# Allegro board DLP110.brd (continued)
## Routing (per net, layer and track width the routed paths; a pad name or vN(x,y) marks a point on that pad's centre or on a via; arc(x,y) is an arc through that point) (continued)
P1_A2: length 49.8
  TOP w0.267: v1(25.15,9.14) 25.41,9.41 27.48,9.41 27.75,9.67 J9.63 ; RN1.8 13.88,44.41 v1(14.1,44.18)
  05_SIG2 w0.102: v1(14.1,44.18) 14.82,43.46 16.75,43.46 19.18,41.03 19.18,36.45 22.99,32.64 22.99,25.78 24.13,24.64 24.13,19.65 24.64,19.15 24.64,9.65 v1(25.15,9.14)
  BOTTOM w0.267: v1(25.15,9.14) 25.4,9.4 27.48,9.4 27.75,9.66 J500.63
P1_A3: length 52.5
  TOP w0.267: J9.62 27.25,6.03 27.15,6.12 25.88,6.12 v1(25.07,6.93) ; v1(12.89,43.94) 12.89,44.95 13.38,45.44 RN1.7
  05_SIG2 w0.102: v1(25.07,6.93) 25.07,8.41 24.27,9.21 24.27,18.97 23.72,19.52 23.72,24.48 22.58,25.61 22.58,32.28 18.67,36.19 18.67,40.22 16.76,42.13 14.7,42.13 v1(12.89,43.94)
  BOTTOM w0.267: J500.62 27.25,5.97 27.08,6.13 25.87,6.13 v1(25.07,6.93)
P1_A4: length 51.2
  TOP w0.267: J9.61 24.93,11.09 v1(23.5,9.65) ; RN1.6 13.3,45.94 v1(11.85,44.49)
  05_SIG2 w0.102: v1(11.85,44.49) 11.85,43.61 18.22,37.24 18.22,35.89 22.05,32.05 22.05,25.44 23.15,24.34 23.15,19.51 23.8,18.85 23.8,9.96 v1(23.5,9.65)
  BOTTOM w0.267: v1(23.5,9.65) 24.71,10.87 J500.61
P1_A5: length 51.3
  TOP w0.267: v1(22.35,6.86) 21.75,6.25 J9.60 ; v1(11.54,45.82) 12.55,45.82 13.17,46.44 RN1.5
  05_SIG2 w0.102: v1(11.54,45.82) 11.2,45.47 11.2,43.64 17.65,37.19 17.65,35.69 21.55,31.79 21.55,25.2 22.78,23.98 22.78,19.27 23.38,18.67 23.38,11.57 22.35,10.54 v1(22.35,6.86)
  BOTTOM w0.267: v1(22.35,6.86) 21.75,6.25 J500.60
P1_A6: length 45.3
  TOP w0.267: v1(12.45,46.74) 12.65,46.94 RN1.4 ; v1(22.48,12.32) 21.75,11.59 J9.59
  05_SIG2 w0.102: v1(12.45,46.74) 11.56,46.74 10.72,45.89 10.72,43.56 17.01,37.27 17.01,35.57 21.04,31.54 21.04,15.78 22.48,14.34 v1(22.48,12.32)
  BOTTOM w0.267: J500.59 21.75,11.59 v1(22.48,12.32)
P1_A7: length 52.7
  TOP w0.267: v1(10.37,46.93) 11.72,46.93 12.23,47.44 RN1.3 ; J9.58 v1(21.25,6.97)
  05_SIG2 w0.102: v1(21.25,6.97) 21.25,12.71 20.41,13.55 20.41,13.92 20.02,14.31 20.02,31.03 13.99,37.06 13.99,38.94 9.66,43.27 9.66,46.3 10.29,46.93 v1(10.37,46.93)
  BOTTOM w0.267: J500.58 v1(21.25,6.97)
P1_A8: length 47.5
  TOP w0.267: v1(11.44,47.65) 11.88,48.09 13.12,48.09 13.27,47.94 RN1.2 ; v1(21.84,13.21) 21.25,12.61 J9.57
  05_SIG2 w0.102: v1(21.84,13.21) 21.84,14 20.53,15.31 20.53,31.29 14.41,37.4 14.41,39.13 10.15,43.39 10.15,45.83 11.24,46.92 11.24,47.45 v1(11.44,47.65)
  BOTTOM w0.267: J500.57 21.25,12.61 v1(21.84,13.21)
P1_A9: length 55.4
  TOP w0.267: J9.56 20.75,6.36 v1(20.08,7.04) ; RN1.1 13.63,48.44 13.37,48.69 10.89,48.69 v1(10.28,48.09)
  05_SIG2 w0.102: v1(20.08,7.04) 19.19,7.92 19.19,13.61 19.6,14.03 19.6,30.69 15.97,34.32 15.09,34.32 9.25,40.16 9.25,46.74 10.28,47.78 v1(10.28,48.09)
  BOTTOM w0.267: J500.56 20.75,6.36 v1(20.08,7.04)
P1_ACTDATA: length 51.7
  TOP w0.267: v1(34.42,8.99) 34.34,8.99 33.75,9.58 J9.87 ; v1(46.02,49.1) 44.83,49.1 R570.2
  05_SIG2 w0.102: v1(46.02,49.1) 42.77,45.84 42.77,42.09 39.98,39.29 39.98,29.52 36.98,26.53 36.98,17.59 33.18,13.79 33.18,10.23 v1(34.42,8.99)
  BOTTOM w0.267: v1(34.42,8.99) 33.75,9.66 J500.87
P1_B0: length 31.5
  TOP w0.267: v1(31.42,34.38) 31.42,35.78 31.11,36.09 R19.2 ; v1(30.61,12.7) 30.75,12.56 J9.75
  05_SIG2 w0.102: v1(30.61,12.7) 30.61,13.96 35.26,18.61 35.26,30.19 31.42,34.03 v1(31.42,34.38)
  BOTTOM w0.267: J500.75 30.75,12.43 v1(30.61,12.7)
P1_B1: length 38.3
  TOP w0.267: R18.2 29.72,36.27 v1(30.58,35.4) ; J9.74 30.25,6.64 v1(30.79,7.18)
  05_SIG2 w0.102: v1(30.79,7.18) 30.04,7.94 30.04,10.09 29.74,10.39 29.74,13.36 30.07,13.69 30.07,14.01 30.6,14.53 30.6,15.63 31.78,16.81 31.78,19.99 33.64,21.86 33.64,31.08 30.58,34.14 v1(30.58,35.4)
  BOTTOM w0.267: v1(30.79,7.18) 30.25,6.64 J500.74
P1_B2: length 34.2
  TOP w0.267: v1(29.97,14.78) 30.12,14.63 30.12,13.29 29.93,13.1 29.93,12.52 30.25,12.2 J9.73 ; v1(29.89,33.54) 29.69,33.74 29.69,35.38 28.29,36.78 RN2.8
  05_SIG2 w0.102: v1(29.97,14.78) 30.01,14.82 30.01,15.88 31.18,17.06 31.18,20.06 32.99,21.87 32.99,31.22 30.67,33.54 v1(29.89,33.54)
  BOTTOM w0.267: J500.73 30.25,12.2 29.95,12.5 29.95,13.2 30.12,13.42 30.12,14.63 v1(29.97,14.78)
P1_B3: length 44.2
  TOP w0.267: RN2.7 27.79,36.49 28.84,35.44 28.84,33.13 v1(30,31.97) ; v1(28.47,2.59) 29.75,3.86 J9.72
  03_SIG1 w0.147: v1(28.47,2.59) 26.92,4.14 26.92,7.66 27.44,8.18 27.44,9.17 26.69,9.92 26.69,12.78 27.28,13.37 27.28,16.63 30.23,19.58 30.23,31.74 v1(30,31.97)
  BOTTOM w0.267: J500.72 29.75,3.86 v1(28.47,2.59)
P1_B4: length 34.2
  TOP w0.267: RN2.6 27.29,36.02 v1(27.69,35.63) ; v1(29.41,13.97) 29.41,12.43 29.75,12.1 J9.71
  05_SIG2 w0.102: v1(29.41,13.97) 29.28,14.1 29.28,16.1 30.61,17.43 30.61,20.01 32.43,21.83 32.43,31.02 30.59,32.86 29.61,32.86 29.24,33.23 29.24,35.23 28.84,35.63 v1(27.69,35.63)
  BOTTOM w0.267: J500.71 29.75,12.1 29.41,12.43 v1(29.41,13.97)
P1_B5: length 36.8
  TOP w0.267: RN2.5 26.83,37.16 26.83,35.27 v1(27.66,34.45) ; J9.70 29.25,6.52 v1(29.67,6.93)
  05_SIG2 w0.102: v1(29.67,6.93) 29.67,9.65 29.17,10.15 29.17,12.98 28.67,13.48 28.67,16.4 30.1,17.83 30.1,30.43 28.88,31.65 28.88,33.23 v1(27.66,34.45)
  BOTTOM w0.267: J500.70 29.25,6.52 v1(29.67,6.93)
P1_B6: length 34.2
  TOP w0.267: v1(28.96,9.18) 29.25,9.47 J9.69 ; RN2.4 26.29,34.73 v1(27.81,33.21)
  05_SIG2 w0.102: v1(28.96,9.18) 28.65,9.49 28.65,12.84 28.23,13.27 28.23,16.89 29.71,18.37 29.71,30.29 28.47,31.53 28.47,32.56 v1(27.81,33.21)
  BOTTOM w0.267: v1(28.96,9.18) 29.25,9.47 J500.69
P1_B7: length 37.5
  TOP w0.267: RN2.3 25.79,35.69 25.69,35.59 25.69,34.45 v1(25.45,34.21) ; J9.68 v1(28.75,7.15)
  05_SIG2 w0.102: v1(25.45,34.21) 25.45,33.84 27.6,31.69 27.6,30.43 28.62,29.41 28.62,28.66 27.77,27.82 27.77,26.58 26.83,25.64 26.83,20.59 27.1,20.32 27.1,13.84 28.19,12.75 28.19,9.02 28.98,8.23 28.98,7.37 v1(28.75,7.15)
  BOTTOM w0.267: J500.68 v1(28.75,7.15)
P1_B8: length 31.9
  TOP w0.267: v1(27.53,12.57) 27.56,12.55 28.32,12.55 28.75,12.12 J9.67 ; RN2.2 25.29,35.97 24.94,35.62 v1(24.94,35.2)
  05_SIG2 w0.102: v1(27.53,12.57) 26.67,13.43 26.67,19.7 26.32,20.05 26.32,25.76 27.24,26.68 27.24,31.49 24.78,33.96 24.78,35.03 v1(24.94,35.2)
  BOTTOM w0.267: v1(27.53,12.57) 28.38,12.57 28.75,12.21 J500.67
P1_B9: length 37.3
  TOP w0.267: v1(27.64,7.21) 28.25,6.6 J9.66 ; RN2.1 24.79,36.41 v1(24.6,36.21)
  05_SIG2 w0.102: v1(24.6,36.21) 24.26,35.87 24.26,33.89 26.84,31.31 26.84,26.88 25.88,25.93 25.88,19.97 26.16,19.7 26.16,12.82 27.64,11.34 v1(27.64,7.21)
  BOTTOM w0.267: J500.66 28.25,6.6 v1(27.64,7.21)
P1_C0: length 49.7
  TOP w0.267: R31.2 v1(46.14,47.55) ; J9.85 33.25,9.17 v1(33.45,8.97)
  03_SIG1 w0.147: v1(46.14,47.55) 45.53,47.55 42.94,44.95 42.94,41.26 40.85,39.18 40.85,29.91 39.45,28.51 39.45,17.19 37.25,14.99 37.25,13.04 33.45,9.25 v1(33.45,8.97)
  BOTTOM w0.267: v1(33.45,8.97) 33.25,9.17 J500.85
P1_C1: length 52.2
  TOP w0.267: J9.84 32.75,3.77 v1(33.43,3.09) ; R30.2 v1(44.81,45.17)
  03_SIG1 w0.147: v1(44.81,45.17) 43.84,44.21 43.84,40.88 41.35,38.39 41.35,29.74 40.12,28.51 40.12,16.94 37.71,14.53 37.71,8.27 36.56,7.12 36.56,6.21 v1(33.43,3.09)
  BOTTOM w0.267: J500.84 32.75,3.77 v1(33.43,3.09)
P1_C2: length 35.9
  TOP w0.267: v1(39.32,31.55) 39.32,35.25 37.31,37.26 RN4.8 ; J9.83 32.75,9.38 v1(32.49,9.12)
  03_SIG1 w0.147: v1(39.32,31.55) 38.49,30.72 38.49,16.96 36.8,15.27 36.8,13.43 v1(32.49,9.12)
  BOTTOM w0.267: v1(32.49,9.12) 32.75,9.38 J500.83
P1_C3: length 42.2
  TOP w0.267: v1(32.38,2.98) 32.25,3.12 J9.82 ; v1(38.32,32.23) 38.32,35.33 36.81,36.84 RN4.7
  03_SIG1 w0.147: v1(32.38,2.98) 32.28,3.09 32.28,7.87 31.88,8.27 31.88,10.78 33.31,12.22 33.31,13.4 37.44,17.53 37.44,31.34 v1(38.32,32.23)
  BOTTOM w0.267: J500.82 32.25,3.12 v1(32.38,2.98)
P1_C4: length 32.4
  TOP w0.267: RN4.6 36.31,36.38 37.08,35.6 v1(37.08,34.37) ; J9.81 32.25,12.12 32.34,12.21 32.34,13.12 v1(31.75,13.72)
  03_SIG1 w0.147: v1(37.08,34.37) 36.92,34.37 36.18,33.63 36.18,18.15 v1(31.75,13.72)
  BOTTOM w0.267: v1(31.75,13.72) 32.35,13.11 32.35,12.22 32.25,12.12 J500.81
P1_C5: length 44
  TOP w0.267: v1(31.77,2.13) 31.75,2.15 J9.80 ; RN4.5 35.81,35.9 36.32,35.39 36.32,33.59 v1(36.82,33.09)
  03_SIG1 w0.147: v1(31.77,2.13) 31.57,2.33 31.57,5.64 31.78,5.85 31.78,7.77 31.53,8.01 31.53,11.34 32.71,12.51 32.71,13.76 36.82,17.87 v1(36.82,33.09)
  BOTTOM w0.267: v1(31.77,2.13) 31.75,2.15 J500.80
P1_C6: length 30.3
  TOP w0.267: J9.79 31.75,12.57 v1(31.75,12.57) ; v1(35.31,33.63) RN4.4
  03_SIG1 w0.147: v1(31.75,12.57) 31.05,13.28 31.05,14.02 35.55,18.52 35.55,33.38 v1(35.31,33.63)
  BOTTOM w0.267: v1(31.75,12.57) 31.75,12.57 J500.79
P1_C7: length 43.9
  TOP w0.267: v1(30.88,2.53) 31.25,2.9 J9.78 ; RN4.3 34.81,36.08 34.29,35.56 v1(34.29,34.09)
  03_SIG1 w0.147: v1(34.29,34.09) 34.5,33.87 34.5,33.24 35,32.74 35,18.78 30.2,13.98 30.2,13.37 29.92,13.1 29.92,12.48 30.47,11.94 30.94,11.94 31.19,11.69 31.19,7.7 31.39,7.51 31.39,6.35 30.88,5.84 v1(30.88,2.53)
  BOTTOM w0.267: v1(30.88,2.53) 31.25,2.9 J500.78
P1_C8: length 36
  TOP w0.267: v1(33.45,33.4) 33.45,35.55 34.31,36.41 RN4.2 ; v1(30.61,9.14) 31.25,9.79 J9.77
  03_SIG1 w0.147: v1(30.61,9.14) 30.61,10.88 29.4,12.08 29.4,12.85 28.65,13.6 28.65,14.7 32.34,18.39 32.34,21.42 33.45,22.53 v1(33.45,33.4)
  BOTTOM w0.267: J500.77 31.25,9.28 31.11,9.14 v1(30.61,9.14)
P1_C9: length 42.6
  TOP w0.267: v1(32.53,34.45) 32.53,35.4 33.81,36.68 RN4.1 ; v1(29.95,2.95) 30.75,3.75 J9.76
  03_SIG1 w0.147: v1(29.95,2.95) 30.25,3.25 30.25,8.11 29.9,8.46 29.9,10.82 28.83,11.88 28.83,12.71 28.18,13.36 28.18,16.02 30.74,18.59 30.74,22.13 32.53,23.92 v1(32.53,34.45)
  BOTTOM w0.267: v1(29.95,2.95) 30.75,3.75 J500.76
P1_FIELD: length 83.8
  TOP w0.267: v1(10.65,52.46) 11.29,53.09 11.29,54.07 11.79,54.57 R571.2 13.11,56.03 R39.1 ; J9.88 33.75,6.91 v1(33.96,7.12)
  05_SIG2 w0.102: v1(33.96,7.12) 32.8,5.97 18.46,5.97 17.64,6.79 17.64,13.36 19.22,14.94 19.22,30.31 15.82,33.71 14.85,33.71 11.41,37.15 10.11,37.15 8.72,38.54 8.72,47.41 10.27,48.96 12.27,48.96 13.1,49.79 13.1,51.48 12.48,52.11 11.01,52.11 v1(10.65,52.46)
  BOTTOM w0.267: J500.88 33.75,6.91 v1(33.96,7.12)
P1_HSYNC: length 59
  TOP w0.267: v1(47.26,48.66) 47.26,49.24 48.36,50.33 R569.2 ; v1(32.91,7.06) 33.25,6.72 J9.86
  05_SIG2 w0.102: v1(32.91,7.06) 31.59,8.38 31.59,9.95 32.46,10.82 32.46,14.59 35.94,18.08 35.94,30.88 39.03,33.97 39.03,43.91 44.86,49.74 46.58,49.74 47.26,49.06 v1(47.26,48.66)
  BOTTOM w0.267: v1(32.91,7.06) 33.25,6.72 J500.86
P1_VSYNC: length 66.1
  TOP w0.267: R32.2 v1(49.51,52.96) ; v1(21.08,13.84) 20.75,13.51 J9.55
  BOTTOM w0.267: v1(49.51,52.96) 47.23,52.96 41.72,47.46 41.72,32.36 38.96,29.6 38.96,20.28 35.69,17.02 28.32,17.02 26.04,14.73 21.97,14.73 v1(21.08,13.84) 20.75,13.51 J500.55
P1P2V_MAIN: length 9.3
  TOP w0.267: J9.4 7.75,3.56 7.62,3.43 v1(7.11,3.43) 7.25,3.57 J9.2
  TOP w0.381: C36.1 7.11,3.31 v1(7.11,3.43)
  BOTTOM w0.279: J500.2 7.25,3.57 ; 7.25,3.57 7.5,3.57 7.75,3.81 J500.4 ; 7.25,3.57 v1(7.11,3.43)
  BOTTOM w0.381: C36.1 6.48,2.79 v1(7.11,3.43)
P1P8V_MAIN: length 8.8
  TOP w0.267: v1(8.38,3.43) 8.38,3.31 C37.1 ; v1(8.38,3.43) 8.75,3.8 J9.8 ; v1(8.38,3.43) 8.25,3.56 J9.6
  BOTTOM w0.279: J500.6 8.25,3.56 v1(8.38,3.43) 8.75,3.8 J500.8
  BOTTOM w0.381: C37.1 7.75,2.79 v1(8.38,3.43)
P2.0: length 11.6
  TOP w0.267: U517.19 10.9,27.06 10.23,26.39 10.23,25.38 9.43,24.58 3.87,24.58 JP1.1
P2_CLK: length 50.8
  TOP w0.267: J9.14 v1(10.25,7.05)
  03_SIG1 w0.147: v1(32.26,36.7) 32.08,36.52 29.68,36.52 28.77,35.6 28.77,31.25 29.1,30.91 29.1,27.86 25.52,24.27 25.52,14.46 22.47,11.4 16.28,11.4 11.92,7.05 v1(10.25,7.05)
  BOTTOM w0.267: R34.2 31.8,37.16 v1(32.26,36.7) ; J500.14 v1(10.25,7.05)
P2_HSYNC: length 63.8
  TOP w0.267: J9.46 18.25,6.54 v1(18.88,7.17) ; R572.2 v1(41.94,51.05)
  03_SIG1 w0.147: v1(18.88,7.17) 21.32,9.61 22.09,9.61 26.43,13.95 26.43,16.93 29.75,20.25 29.75,31.28 29.22,31.81 29.22,35.03 30.23,36.05 36.27,36.05 41.94,41.72 v1(41.94,51.05)
  BOTTOM w0.267: v1(18.88,7.17) 18.25,6.54 J500.46
P2_VSYNC: length 70.7
  TOP w0.267: v1(14.01,13.82) 12.53,12.34 11.01,12.34 10.75,12.08 J9.15 ; R568.2 v1(42.11,52.96)
  03_SIG1 w0.147: v1(42.11,52.96) 40.75,51.59 40.75,42 36.38,37.63 28.72,37.63 27.01,35.92 27.01,31.97 27.45,31.53 27.45,29.67 27.07,29.29 27.07,26.44 24.48,23.84 24.48,17.6 21.39,14.52 14.7,14.52 v1(14.01,13.82)
  BOTTOM w0.267: v1(14.01,13.82) 12.55,12.36 11,12.36 10.75,12.1 J500.15
P2P5V_MAIN: length 8.4
  TOP w0.267: J9.10 9.25,3.83 v1(9.65,3.43) ; v1(9.65,3.43) 9.75,3.53 J9.12 ; v1(9.65,3.43) 9.78,3.3 C38.1
  BOTTOM w0.279: J500.12 9.75,3.53 v1(9.65,3.43) 9.25,3.83 J500.10
  BOTTOM w0.381: v1(9.65,3.43) 9.78,3.3 C38.1
P3P3V_AFE: length 6.7
  TOP w0.381: U7.16 C3.2 v1(57.33,50.79) ; R15.1 v1(52.62,50.6) ; J6.3 v1(54.15,36.31)
  BOTTOM w0.381: R47.1 v1(57.39,35.06) ; R48.1 v1(57.39,33.81)
  vias: v1(48.61,62.28) v1(48.61,61.06) v1(49.88,62.28) v1(49.88,61.06) v1(51.54,36.44) v1(51.53,35.32)
P3P3V_AFE_ADJ_A: length 1.5
  TOP w0.381: U14.8 55.01,58.21 R53.1
P3P3V_AFE_ADJ_B: length 1.5
  TOP w0.267: U14.6 56.31,58.24 R52.1
P3P3V_AFE_EN: length 5.6
  TOP w0.381: v1(58.39,59.56) 58.68,59.85 58.68,61.88 C608.2 58.2,63.86 R575.2
  BOTTOM w0.381: U505.5 v1(58.39,59.56)
P3P3V_AFE_FB: length 14.5
  TOP w0.254: U14.7 55.66,57.44
  TOP w0.381: v1(56.16,64.55) 55.66,64.04 55.66,57.44
  BOTTOM w0.381: U505.4 56.11,61.44 R574.1 56.34,62.36 R573.1 55.26,64.67 C607.1 56.05,64.67 v1(56.16,64.55)
P3P3V_ITE: length 47.3
  TOP w0.254: U517.41 21.6,26.56 22.13,26.03 v1(22.13,23.73)
  TOP w0.508: C681.1 R621.2 R620.2 20.45,36.8 19.9,37.34 17.35,37.34 16.56,38.14 15.26,38.14 v1(15.05,37.93) 14.73,37.61 R622.2 ; v1(3.94,15.49) 4.22,15.77 R623.2 ; R625.1 v1(14.22,20.83)
  BOTTOM w0.381: R624.2 10.31,50.01 10.31,50.61 v1(10.51,50.81)
  BOTTOM w0.508: 20.8,22.12 R619.1 21.64,23.24 v1(22.13,23.73) 22.13,24.65 21.38,25.4 R614.1 ; 20.8,22.12 20.16,21.48 R616.1 R617.1 14.88,21.48 v1(14.22,20.83) ; 20.8,22.12 22.61,20.32 v1(22.61,17.78)
  BOTTOM w0.762: FB2.2 15.21,69.24 v1(15.21,64.82) v1(16.32,64.82) 19.13,64.82 FB4.2 ; v1(7.13,57.2) 7.13,56.63 FB1.2
  vias: v1(10.73,34.79) v1(10.73,33.52) v1(12,34.79) v1(12,33.52) v1(46.73,58.29) v1(46.73,57.02) v1(48,58.29) v1(48,57.02) v1(49.9,67.89) v1(49.9,66.62) v1(49.9,65.35) v1(51.17,67.89) v1(51.17,66.62) v1(51.17,65.35)
P3P3V_LAB_RES: length 1.2
  TOP w0.508: R54.2 v1(51.65,69.75)
  vias: v1(52.59,66.46) v1(52.59,65.19) v1(53.42,57.78) v1(53.74,60.96) v1(53.81,63.01) v1(53.86,66.46) v1(53.86,65.19)
P3P3V_MAIN: length 9.2
  TOP w0.305: J9.7 8.75,12.21 v1(8.38,12.57) 8.25,12.44 J9.5
  TOP w0.508: v1(8.38,12.57) 8.13,12.83 C34.1
  BOTTOM w0.267: J500.7 8.75,12.21 v1(8.38,12.57) 8.25,12.44 J500.5
  BOTTOM w0.508: C34.1 8.13,12.83 v1(8.38,12.57)
PCA9539_PU: length 4
  TOP w0.267: v1(48.46,34.36) 49.13,35.04 U8.21
  BOTTOM w0.267: v1(48.46,34.36) 48.54,34.28 R8.2
PCLK: length 6.2
  TOP w0.267: U516.127 33.99,41.88 v1(34.59,41.27)
  BOTTOM w0.267: v1(34.59,41.27) 33.55,40.23 C628.1 33.53,39.62 R34.1
PCSCL: length 40.9
  TOP w0.267: v1(40.36,55.12) 39.29,55.12 38.97,54.8 U516.23
  03_SIG1 w0.147: v1(40.36,55.12) 40.08,55.12 38.18,53.22 38.18,42.83 34.92,39.57 25.95,39.57 22.42,36.04 22.42,34.9 v1(22.14,34.62)
  BOTTOM w0.267: v1(22.14,34.62) 21.12,34.62 20.85,34.35 R608.1 20.83,33.55 R609.2
PCSDA: length 53.3
  TOP w0.267: v1(26.21,30.18) 26.66,29.73 26.66,26.21 v1(27.51,25.36) ; v1(41.16,54.4) U516.22
  03_SIG1 w0.147: v1(26.21,30.18) 26.21,36.45 28.43,38.68 35.71,38.68 39.49,42.45 39.49,51.79 40.96,53.26 40.96,54.2 v1(41.16,54.4)
  BOTTOM w0.267: v1(27.51,25.36) 23.16,25.36 21.08,27.43 R610.2 R607.1
R0X0M: length 20
  TOP w0.114: CN1.9 40.04,75.56 39.66,75.18 39.66,74.57 39.79,74.43 U511.9 39.79,73.94 39.66,73.81 39.66,73.69 39.79,73.55 U511.2 39.79,73.04 39.66,72.9 39.66,72.14 36.1,68.59 35.61,68.59 31.51,64.48 31.51,62.19 31.59,62.11 U516.40
R0X0P: length 20
  TOP w0.114: U516.41 31.19,62.1 31.28,62.19 31.28,64.58 35.52,68.81 36.01,68.81 39.43,72.24 39.43,72.9 39.29,73.04 U511.1 39.29,73.55 39.43,73.69 39.43,73.81 39.29,73.94 U511.10 39.29,74.43 39.43,74.57 39.43,75.18 39.04,75.56 CN1.7
R0X1M: length 20
  TOP w0.114: U516.43 30.39,62.11 30.31,62.2 30.31,62.38 30.47,62.54 30.47,65.11 35.36,70 36.08,70 38.16,72.08 38.16,72.9 38.29,73.04 U510.5 38.29,73.55 38.16,73.69 38.16,73.81 38.29,73.94 U510.6 38.29,74.43 38.16,74.57 38.16,75.18 38.54,75.56 CN1.6
R0X1P: length 20
  TOP w0.114: U516.44 29.99,62.1 30.08,62.19 30.08,62.48 30.24,62.63 30.24,65.21 35.27,70.23 35.99,70.23 37.93,72.18 37.93,72.9 37.79,73.04 U510.4 37.79,73.55 37.93,73.69 37.93,73.81 37.79,73.94 U510.7 37.79,74.43 37.93,74.57 37.93,75.18 37.54,75.56 CN1.4
R0X2M: length 20
  TOP w0.114: CN1.3 37.04,75.56 36.66,75.18 36.66,74.57 36.79,74.43 U510.9 36.79,73.94 36.66,73.81 36.66,73.69 36.79,73.55 U510.2 36.79,73.04 36.66,72.9 36.66,72.25 35.67,71.26 34.46,71.26 29.51,66.31 29.51,62.19 29.59,62.11 U516.45
R0X2P: length 20
  TOP w0.114: U516.46 29.19,62.1 29.28,62.19 29.28,66.41 34.37,71.49 35.57,71.49 36.43,72.35 36.43,72.9 36.29,73.04 U510.1 36.29,73.55 36.43,73.69 36.43,73.81 36.29,73.94 U510.10 36.29,74.43 36.43,74.57 36.43,75.18 36.04,75.56 CN1.1
R0XCM: length 20
  TOP w0.114: CN1.12 41.54,75.56 41.16,75.18 41.16,74.57 41.29,74.43 U511.6 41.29,73.94 41.16,73.81 41.16,73.69 41.29,73.55 U511.5 41.29,73.04 41.16,72.9 41.16,72.1 32.5,63.45 32.5,62.58 32.31,62.39 32.31,62.2 32.39,62.11 U516.38
R0XCP: length 20
  TOP w0.114: CN1.10 40.54,75.56 40.93,75.18 40.93,74.57 40.79,74.43 U511.7 40.79,73.94 40.93,73.81 40.93,73.69 40.79,73.55 U511.4 40.79,73.04 40.93,72.9 40.93,72.2 32.27,63.54 32.27,62.68 32.08,62.49 32.08,62.19 31.99,62.1 U516.39
RX_1V2: length 4.4
  BOTTOM w0.508: FB9.2 17.7,59.82 v1(17.08,60.44) ; FB6.2 14.1,59.44 v1(14.1,58.84) ; FB7.2 16.15,59.54 v1(16.15,59) ; FB5.2 12.07,59.3 v1(12.07,58.92)
  vias: v1(17.2,40.51) v1(17.2,39.22) v1(24.93,66.24) v1(24.93,64.97) v1(26.2,66.24) v1(26.2,64.97) v1(27.47,66.24) v1(27.47,64.97) v1(41.38,22.6) v1(41.38,21.33) v1(42.65,22.6) v1(42.65,21.33) v1(43.92,22.6) v1(43.92,21.33)
RX_APVDD12: length 10.6
  TOP w0.267: 17.81,58.91 18.33,58.4 U516.65
  TOP w0.508: 17.81,58.91 17.56,59.17 17.16,59.17 16.38,59.94 C663.1 C664.1 C665.1 16.08,62.99 v1(16.21,62.87)
  BOTTOM w0.508: FB7.1 16.21,62.18 v1(16.21,62.87)
RX_AVCC12: length 54.2
  TOP w0.267: U516.50 27.59,58.96 v1(28.07,58.48) ; U516.34 33.99,62.39 35.2,63.6 v1(35.2,64)
  03_SIG1 w0.508: v1(10.14,64.49) 13.25,64.49 14.75,65.99 16.94,65.99 18.35,67.4 18.35,68.23 20.37,70.25 30.46,70.25 35.2,65.5 v1(35.2,64) 35.2,63.11 34.33,62.23 30.33,62.23 28.07,59.97 v1(28.07,58.48)
  BOTTOM w0.381: C652.1 v1(35.2,64)
  BOTTOM w0.508: v1(10.14,64.49) v1(10.14,63.26) 10.14,63.26 FB5.1
  BOTTOM w0.762: v1(28.07,58.48) 28.6,59.02 C653.1
RX_AVCC33: length 24.5
  TOP w0.267: U516.58 24.39,58.81 v1(24.21,58.62) ; v1(30.61,58.46) 30.79,58.65 U516.42 ; U516.37 32.79,57.38 v1(33.02,57.15) ; U516.53 26.39,58.96 26.04,58.6 v1(26.04,57.65) ; U516.63 22.39,58.74 22.66,58.48 23.04,58.48 v1(23.11,58.55) ; v1(29.34,58.29) 28.79,58.84 U516.47
  BOTTOM w0.508: C644.1 23.11,59.57 v1(23.11,58.55) ; v1(33.02,57.15) C655.1 ; v1(26.04,57.65) 26.04,56.7 C645.1 ; v1(29.34,58.29) 29.29,58.24 C646.1 ; v1(24.21,58.62) 24.21,57.22 C647.1 ; C654.1 31.14,57.93 v1(30.61,58.46)
  vias: v1(42.23,61.14) v1(42.23,59.87) v1(42.23,58.6) v1(42.23,57.33)
RX_DVDD12: length 17.8
  TOP w0.267: U516.64 21.99,62.06 21.62,62.44 v1(21.2,62.44) ; U516.48 28.39,62.58 v1(28.06,62.91)
  05_SIG2 w0.762: v1(28.06,62.91) 27.59,62.44 v1(21.2,62.44)
  BOTTOM w0.508: C676.1 21.66,61.98 v1(21.2,62.44) ; C678.1 28.73,62.4 28.22,62.91 v1(28.06,62.91)
  BOTTOM w0.762: v1(21.2,62.44) 20.71,61.95 C677.1 18.14,61.95 FB9.1
RX_HPD0: length 20.6
  TOP w0.267: R595.1 v1(39.38,66.41) ; v1(46.39,75.97) 45.77,76.59 CN1.19
  BOTTOM w0.267: D519.2 45.99,80.18 R592.1 45.99,77.04 R590.2 45.89,76.46 v1(46.39,75.97) 46.39,75.12 45.13,73.86 44.06,73.86 39.38,69.18 v1(39.38,66.41)
RX_IVDD12: length 39
  TOP w0.267: v1(34.44,49.66) 34.9,49.2 U516.9 ; U516.97 21.99,42.47 21.73,42.2 21.35,42.2 v1(21.3,42.25) ; v1(38.76,55.52) 38.43,55.2 U516.24 ; U516.84 16.97,50.8 v1(16.7,51.06) ; U516.74 17.79,54.8 v1(17.56,54.57) ; v1(26.52,41.17) 27.19,41.85 U516.110 ; U516.121 31.59,41.98 32.05,41.53 v1(32.05,40.9)
  BOTTOM w0.508: C668.1 18.62,50.72 17.31,50.72 16.97,51.06 v1(16.7,51.06) 16.7,51.98 C667.1 18.06,54.08 v1(17.56,54.57) ; v1(34.44,49.66) 34.62,49.48 C672.1
  BOTTOM w0.762: v1(38.76,55.52) 38.2,54.97 C673.1 37.24,54.97 36.47,54.2 36.47,50.22 C672.1 ; C671.1 27.15,41.81 v1(26.52,41.17) ; v1(32.05,40.9) 32.03,40.92 32.03,42.24 C670.1 ; C669.1 21.59,42.55 v1(21.3,42.25)
  vias: v1(19.85,43.64) v1(20.53,44.57) v1(21.14,43.64)
RX_OVDD: length 58.7
  TOP w0.267: U516.109 26.79,46.12 v1(28.04,47.36) ; U516.88 v1(22.02,49.2) ; U516.13 33.6,50.8 v1(33.55,50.84) ; U516.93 21.46,47.2 v1(21.99,47.73) ; U516.78 23.4,53.2 v1(23.6,53.39) ; U516.6 34.88,48 v1(34.47,47.59) 34.39,47.51 U516.128 ; U516.116 29.59,45.42 29.15,45.86 v1(29.15,47.24) ; U516.100 v1(23.19,47.24) ; v1(31.88,47.37) 31.88,46.74 32.39,46.22 U516.123 ; U516.68 21.38,57.2 v1(22.06,57.89)
  BOTTOM w0.508: v1(22.02,49.2) 20.98,49.2 C636.1 ; C637.1 21.23,54.08 21.92,53.39 v1(23.6,53.39)
  BOTTOM w0.762: v1(21.99,47.73) C633.1 ; C639.1 31.88,46.33 v1(31.88,47.37) ; C638.1 23.19,46.3 v1(23.19,47.24) ; FB1.1 9.91,54.1 C629.1 12.09,53.98 C630.1 C631.1 14.94,53.87 15.62,53.19 ; C635.1 v1(22.06,57.89) ; v1(33.06,47.39) 33.06,46.95 33.43,46.58 C632.1 ; 15.62,53.19 15.62,53.6 v1(16.28,54.26) v1(16.87,53.67) ; 15.62,53.19 R544.1 ; C634.1 v1(28.04,47.36)
RX_OVDD33: length 103.1
  TOP w0.267: v1(34.88,58.65) 35.13,58.4 U516.32
  TOP w0.381: v1(13.34,37.34) R593.2 ; v1(27.9,29.08) 27.9,31.89 26.54,33.25 24.75,33.25 22.22,35.78 v1(21.69,35.78)
  03_SIG1 w0.381: v1(13.59,67.94) 12.5,69.03 9.53,69.03 7.24,66.74 7.24,59.39 5.17,57.31 5.17,42.17 9.64,37.7 12.97,37.7 v1(13.34,37.34)
  05_SIG2 w0.381: v1(13.59,67.94) 15.64,65.9 16.73,65.9 18.79,63.84 18.79,63.14 20.94,60.98 32.55,60.98 v1(34.88,58.65)
  BOTTOM w0.381: R610.1 23.07,27.8 26.61,27.8 v1(27.9,29.08) ; v1(21.69,35.78) 19.93,35.78 R609.1 16.23,35.28 14.18,37.34 v1(13.34,37.34)
  BOTTOM w0.508: FB2.1 14.84,71.06 C641.1 C642.1 13.59,69.39 v1(13.59,67.94)
RX_PVCC12: length 34.2
  TOP w0.267: v1(33.5,58.42) 33.5,58.99 33.59,59.08 U516.35 ; U516.51 27.19,57.91 v1(27.18,57.89)
  05_SIG2 w0.508: 27.18,59.18 v1(27.18,57.89) ; 27.18,59.18 27.64,59.65 32.28,59.65 v1(33.5,58.42) ; 27.18,59.18 27,59.36 20.44,59.36 17.43,62.37 v1(17.43,63)
  BOTTOM w0.508: C661.1 27.17,59.71 27.17,57.9 v1(27.18,57.89) ; FB6.1 13.72,63.27 C662.1 15.16,63.4 15.52,63.76 16.67,63.76 v1(17.43,63)
  BOTTOM w0.762: C660.1 v1(33.5,58.42)
RX_PVCC33: length 22.1
  TOP w0.267: U516.36 33.19,62.34 33.95,63.1 v1(33.95,63.49) ; U516.52 v1(26.79,63.5)
  BOTTOM w0.508: v1(26.79,63.5) 27.15,63.14 C650.1
  BOTTOM w0.762: C648.1 33.5,63.04 v1(33.95,63.49) 33.51,63.93 27.23,63.93 v1(26.79,63.5) 26.64,63.65 C649.1 22.33,63.65 FB4.1
SCL_0: length 115.7
  TOP w0.267: U7.6 v1(54.31,45.26) 54.31,49.32 55.66,50.67 U14.2 ; 24.89,31.62 24.01,30.74 23.31,30.74 22.3,29.73 22.3,27.66 22.92,27.05 22.92,21.49 27.26,17.14 37.56,17.14 40.62,14.08 40.62,13.19 v1(40.38,12.94) 40.75,12.57 J9.115 ; J6.1 v1(54.04,33.81) 52.32,32.09 52.32,28.8 52.05,28.54 49.58,28.54 48.63,29.49 48.63,32.85 47.52,33.96 47.52,35.45 47.79,35.71 48.16,35.71 v1(48.39,35.48) 48.59,35.69 U8.22
  03_SIG1 w0.147: v1(54.04,33.81) 53.28,34.57 53.28,38.03 53.68,38.44 53.68,44.35 54.31,44.98 v1(54.31,45.26) ; v1(40.38,12.94) 40.38,13.34 46.3,19.26 46.3,25.03 49.81,28.55 49.81,34.83 48.96,35.68 48.59,35.68 v1(48.39,35.48)
  BOTTOM w0.267: 24.89,31.62 24.64,31.88 R618.2 R608.2 ; J500.115 40.75,12.57 v1(40.38,12.94) ; R48.2 v1(54.04,33.81)
SCL_DDC_CI_1: length 45.8
  TOP w0.267: v1(49.08,44.43) 50.56,45.91 U7.5 ; v1(35.75,14.84) J9.95
  05_SIG2 w0.102: v1(35.75,14.84) 38.22,17.31 38.22,26.2 41.03,29.01 41.03,36.38 v1(49.08,44.43)
  BOTTOM w0.267: v1(35.75,14.84) J500.95
SCL_DDC_CI_2: length 48.2
  TOP w0.267: U7.4 50.34,46.56 49.7,45.93 v1(49.33,45.93) ; J9.113 v1(40.25,8.98)
  03_SIG1 w0.147: v1(49.33,45.93) 44.86,41.46 44.86,30.13 45.57,29.42 45.57,19.38 39.6,13.41 39.6,9.63 v1(40.25,8.98)
  BOTTOM w0.267: J500.113 v1(40.25,8.98)
SCL_HDMI0_DDC_CI: length 49.3
  TOP w0.267: CN1.15 43.04,75.09 42.35,74.4 42.35,69.14 43.14,68.35 R585.1 44.28,68.1 D517.2 R589.1 v1(41.68,66.82) ; v1(50.07,43.23) 50.07,44.2 50.49,44.61 U7.7
  05_SIG2 w0.102: v1(41.68,66.82) 43.21,66.82 45.42,64.62 45.42,56.62 48.52,53.51 48.52,52.15 51.17,49.51 51.17,46.56 50.07,45.47 v1(50.07,43.23)
  BOTTOM w0.267: v1(50.07,43.23) 50.07,44.29 51.14,45.36 51.46,45.36 51.7,45.6 U500.6
SDA_0: length 120.7
  TOP w0.267: U14.3 56.31,50.45 55.02,49.16 v1(55.02,44.08) 55.89,44.08 56.43,44.61 U7.10 ; U8.23 48.59,36.34 v1(48.39,36.54) 48.14,36.29 47.55,36.29 46.95,35.68 46.95,33.72 48.06,32.61 48.06,29.17 49.26,27.96 52.29,27.96 52.89,28.57 52.89,31.63 54.15,32.88 56.21,32.88 56.48,33.15 56.48,34.8 56.21,35.06 J6.2 v1(54.04,35.06) ; JP3.2 24.01,29.97 23.63,29.97 23.08,29.41 23.08,27.98 23.64,27.42 23.64,21.86 27.58,17.92 37.88,17.92 41.4,14.4 41.4,13.16 v1(41.62,12.94) 41.25,12.57 J9.117
  03_SIG1 w0.147: v1(55.02,44.08) 54.16,43.22 54.16,39 54.82,38.34 54.82,35.85 v1(54.04,35.06) ; v1(41.62,12.94) 41.62,13.6 46.95,18.94 46.95,24.76 50.47,28.28 50.47,35.1 49.24,36.34 48.59,36.34 v1(48.39,36.54)
  BOTTOM w0.267: J500.117 41.25,12.57 v1(41.62,12.94) ; R615.2 22.71,30.1 R607.2 24.64,28.83 JP3.2 ; R47.2 v1(54.04,35.06)
SDA_DDC_CI_1: length 48.8
  TOP w0.267: U7.11 56.06,45.26 v1(55.86,45.07) ; J9.93 35.25,12.21 34.89,12.57 v1(34.89,13.52)
  05_SIG2 w0.102: v1(55.86,45.07) 55.86,43.8 55.23,43.17 55.23,41.75 49.52,36.04 49.52,33.56 46.52,30.56 44.41,30.56 39.02,25.17 39.02,16.99 35.54,13.52 v1(34.89,13.52)
  BOTTOM w0.267: v1(34.89,13.52) 34.89,12.55 35.25,12.19 J500.93
SDA_DDC_CI_2: length 54.4
  TOP w0.267: v1(55.85,46.18) 56.12,45.91 U7.12 ; J9.114 v1(40.25,6.96)
  05_SIG2 w0.102: v1(40.25,6.96) 39.62,7.58 39.62,11.07 38.3,12.4 38.3,14.2 39.51,15.41 39.51,24.83 44.82,30.13 46.71,30.13 50.07,33.49 50.07,35.94 55.79,41.66 55.79,42.94 56.51,43.66 56.51,45.52 v1(55.85,46.18)
  BOTTOM w0.267: J500.114 v1(40.25,6.96)
SDA_HDMI0_DDC_CI: length 51.6
  TOP w0.267: CN1.16 43.54,71.44 43.84,71.14 44.67,71.14 44.94,70.88 44.94,69.37 R584.1 D517.1 R591.1 v1(48.57,66.82) ; U7.9 v1(57.33,43.16)
  05_SIG2 w0.102: v1(48.57,66.82) 47.52,65.77 47.52,62.56 46.85,61.88 46.85,59.74 47.37,59.22 47.37,55.77 49.41,53.73 53.39,53.73 57.72,49.4 57.72,43.55 v1(57.33,43.16)
  BOTTOM w0.267: v1(57.33,43.16) 57.13,42.96 54.41,42.96 53.04,44.33 U500.5
SPDIF_DL2: length 2.7
  TOP w0.267: J3.2 7.32,75.18 R605.1
SYSRSTN: length 6.8
  TOP w0.267: R542.1 14.81,50.25 R540.1 15.1,51.94 16.89,51.94 17.63,51.2 U516.83
UART_RX: length 4.4
  TOP w0.267: J9.92 34.75,6.68 v1(35.12,7.05)
  BOTTOM w0.267: v1(35.12,7.05) 34.75,6.68 J500.92
UART_TX: length 4.5
  TOP w0.267: J9.53 20.25,12.64 v1(19.85,13.04)
  BOTTOM w0.267: J500.53 20.25,12.64 v1(19.85,13.04)
VSYNC: length 11.1
  TOP w0.267: R32.1 R568.1 44.81,52.55 44.29,52.04 41.94,52.04 41.05,51.15 39.98,51.15 39.53,51.6 U516.15
WS_DR0_CONN: length 2.6
  TOP w0.267: R2.1 J3.12
XTAL1: length 7.6
  TOP w0.267: v1(10.51,28.13) 10.93,28.55 12.12,28.55 U517.16
  BOTTOM w0.267: C680.1 11.23,28.48 10.86,28.48 v1(10.51,28.13) 10.2,28.44 8.31,28.44 8,28.13 Y-1.2
XTAL2: length 7.6
  TOP w0.267: U517.15 12.12,29.08 10.93,29.08 v1(10.51,29.5)
  BOTTOM w0.267: C682.1 11.23,29.15 10.86,29.15 v1(10.51,29.5) 10.11,29.1 8.17,29.1 7.83,29.44 7.83,30.38 Y-1.1
N17176927: length 29
  TOP w0.267: X1.1 3.81,50.94 4.48,50.27 5.62,50.27 5.97,50.62 5.97,52.21 6.24,52.48 C17.2 R29.1 7.8,50.47 8.17,50.47 8.73,51.03 8.73,55.41 11.19,57.87 17.11,57.87 17.24,58 U516.66
N17176943: length 29
  TOP w0.267: X1.2 3.81,49.08 4.48,49.75 5.75,49.75 6.07,49.43 6.07,47.87 6.33,47.6 C18.2 R29.2 8.02,49.82 8.27,49.82 9.48,51.04 9.48,55.25 11.58,57.35 17.4,57.35 17.65,57.6 U516.67
N17208762: length 8.5
  TOP w0.267: v1(34.17,56.95) 34.81,57.6 U516.30
  BOTTOM w0.267: R611.2 R612.1 C679.1 36.05,57.61 34.83,57.61 v1(34.17,56.95)
N17213119: length 34.8
  TOP w0.267: R11.2 v1(8.99,71.53) ; U516.77 22.5,53.6 v1(23.44,54.53)
  05_SIG2 w0.102: v1(23.44,54.53) 22.6,53.7 21.98,53.7 21.44,54.24 21.44,55.18 19.04,57.58 15.67,57.58 15.06,58.18 13.8,58.18 13.43,58.56 13.43,60.1 12.04,61.49 10.34,61.49 8.01,63.82 8.01,70.55 v1(8.99,71.53)
N17213121: length 29.9
  TOP w0.267: v1(22.34,54.32) 22.02,54 U516.76 ; v1(10.54,70.23) 10.41,70.1 R10.2
  05_SIG2 w0.102: v1(10.54,70.23) 8.48,68.17 8.48,63.93 10.3,62.11 12.16,62.11 14.18,60.09 14.18,59.71 15.91,57.98 19.13,57.98 22.34,54.76 v1(22.34,54.32)
N17213123: length 25.9
  TOP w0.267: v1(10.03,68.07) 9.53,67.56 R9.2 ; U516.75 21.38,54.4 22.41,55.43 v1(22.61,55.43)
  05_SIG2 w0.102: v1(22.61,55.43) 22.27,55.43 19.19,58.51 17.53,58.51 16.42,59.62 15.33,59.62 11.07,63.88 9.8,63.88 9,64.68 9,67.04 v1(10.03,68.07)
N17213125: length 22.8
  TOP w0.267: U516.73 21.39,55.2 22.33,56.13 v1(23.52,56.13) ; R3.2 9.46,65.49 v1(10.05,65.49)
  05_SIG2 w0.102: v1(23.52,56.13) 23.33,56.32 22.16,56.32 19.43,59.05 17.57,59.05 16.49,60.12 15.68,60.12 10.31,65.49 v1(10.05,65.49)
N17213127: length 24.6
  TOP w0.267: R2.2 9.55,61.93 v1(9.55,61.37) ; U516.79 22.97,52.8 v1(23.4,52.37)
  05_SIG2 w0.102: v1(9.55,61.37) 9.88,61.37 10.35,60.9 12.03,60.9 12.91,60.02 12.91,58.28 13.48,57.71 14.71,57.71 15.21,57.21 18.77,57.21 21.04,54.94 21.04,53.85 21.62,53.27 22.73,53.27 23.4,52.6 v1(23.4,52.37)
N17213129: length 23.8
  TOP w0.267: v1(9.92,60.02) 9.74,60.2 R1.2 ; v1(23.41,50.92) 23.41,51.32 22.33,52.4 U516.80
  05_SIG2 w0.102: v1(23.41,50.92) 23.41,51.32 22.51,52.22 22.15,52.22 20.49,53.89 20.49,54.79 18.5,56.78 14.83,56.78 14.3,57.3 12.42,57.3 10.86,58.86 10.86,59.24 10.09,60.02 v1(9.92,60.02)
N17216227: length 20.9
  TOP w0.267: R606.2 8.39,58.07 v1(8.39,57.56) ; U516.81 21.64,52 v1(22.15,51.49)
  05_SIG2 w0.102: v1(8.39,57.56) 9.2,57.56 10.54,56.23 18.46,56.23 20.01,54.67 20.01,53.62 v1(22.15,51.49)
N17284357: length 32.6
  TOP w0.267: v1(22.61,56.95) 22.21,56.55 21.98,56.55 21.43,56 U516.71 ; R605.2 8.22,76.94 8.93,76.24 8.93,74.48 v1(8.51,74.07)
  05_SIG2 w0.102: v1(22.61,56.95) 22.04,56.95 19.48,59.51 18.22,59.51 17.72,60.01 17.72,60.72 17.24,61.21 15.44,61.21 12.27,64.38 12.27,70.23 8.51,73.99 v1(8.51,74.07)
N17675272: length 5.2
  TOP w0.267: U516.102 23.99,40.76 23.5,40.26 R21.1
N17675274: length 5.7
  TOP w0.267: U516.101 23.59,41.34 21.97,39.72 R20.1
N17675276: length 11.8
  TOP w0.267: RN1.9 15.88,44.94 20.02,40.8 22.12,40.8 22.79,41.48 U516.99
N17675278: length 10.8
  TOP w0.267: RN1.10 16.31,45.44 20.22,41.53 21.99,41.53 22.39,41.93 U516.98
N17675280: length 4.7
  TOP w0.267: U516.95 17.69,46.4 17.24,45.94 RN1.11
N17675282: length 4.7
  TOP w0.267: U516.94 17.46,46.8 17.1,46.44 RN1.12
N17675284: length 4.8
  TOP w0.267: U516.92 17.69,47.6 17.03,46.94 RN1.13
N17675286: length 4.7
  TOP w0.267: RN1.14 16.7,47.44 17.26,48 U516.91
N17675288: length 4.7
  TOP w0.267: RN1.15 15.89,47.94 16.34,48.4 U516.90
N17675290: length 4.7
  TOP w0.267: RN1.16 15.37,48.44 15.73,48.8 U516.89
N17726793: length 5
  TOP w0.267: v1(34.26,55.69) 34.97,56.4 U516.27
  BOTTOM w0.267: R5.1 35.09,56.52 v1(34.26,55.69)
N17741544: length 6.1
  TOP w0.267: U516.87 17.69,49.6 v1(17.6,49.5)
  BOTTOM w0.267: v1(17.6,49.5) 16.84,48.74 R543.2 R544.2
N17791476: length 47.7
  TOP w0.267: U516.16 v1(34.39,52) ; R571.1 15.39,54.57 v1(16.13,55.31)
  03_SIG1 w0.147: v1(16.13,55.31) 15.6,54.78 15.6,46 21.56,40.04 32.5,40.04 33.37,40.9 33.37,44.34 36.1,47.08 36.1,51.57 35.67,52 v1(34.39,52)
N17816955: length 13.8
  TOP w0.267: U516.85 17.86,50.4 17.6,50.13 16.44,50.13 15.66,49.35 12.12,49.35 11.99,49.23 10.4,49.23 9.47,48.3 9.47,46.15 R594.1
N17949374: length 5.5
  TOP w0.267: R541.1 16.12,53.12 16.37,52.87 16.77,52.87 18.05,51.6 U516.82
N17950232: length 4.3
  TOP w0.267: U516.18 34.62,52.8 v1(34.09,53.32)
  BOTTOM w0.267: TP1.1 34.43,52.98 v1(34.09,53.32)
N17950739: length 5.8
  TOP w0.267: R595.2 34.39,61.87 U516.33
N17954990: length 7.5
  TOP w0.267: R602.1 42.66,54.32 42.4,54.32 40.92,52.84 39.81,52.84 39.05,53.6 U516.20
N17966004: length 2.7
  TOP w0.267: D520.1 R594.2
N18010922: length 5.6
  TOP w0.267: RN2.10 27.79,39.39 28.79,40.39 U516.114
N18010926: length 5.6
  TOP w0.267: U516.115 29.19,40.12 28.29,39.22 RN2.9
N18010974: length 5.1
  TOP w0.267: U516.117 29.99,40.46 29.72,40.18 R18.1
N18010978: length 5.3
  TOP w0.267: R19.1 31.11,39.74 30.39,40.46 U516.118
N18011121: length 5.7
  TOP w0.267: U516.113 28.39,40.84 27.29,39.74 RN2.11
N18011123: length 5.7
  TOP w0.267: RN2.12 26.79,39.9 27.99,41.1 U516.112
N18011125: length 5.7
  TOP w0.267: RN2.13 26.29,40.06 27.59,41.36 U516.111
N18011127: length 5.4
  TOP w0.267: U516.108 26.39,41.91 25.79,41.31 RN2.14
N18011129: length 5.3
  TOP w0.267: U516.106 25.59,41.68 25.29,41.38 RN2.15
N18011131: length 5.4
  TOP w0.267: RN2.16 24.79,41.53 25.19,41.93 U516.105
N18011461: length 12.9
  TOP w0.267: RN4.10 36.81,39.26 40.51,42.97 40.51,45.74 39.05,47.2 U516.4
N18011465: length 14.3
  TOP w0.267: RN4.9 37.31,38.82 41.26,42.77 41.26,46.28 39.94,47.6 U516.5
N18011513: length 7.3
  TOP w0.267: U516.7 38.38,48.4 38.66,48.12 40.55,48.12 42.14,46.53 42.7,46.53 R30.1
N18011517: length 6.9
  TOP w0.267: U516.8 41.16,48.8 42.41,47.55 R31.1
N18011660: length 11.9
  TOP w0.267: RN4.11 36.31,39.65 39.79,43.13 39.79,45.67 38.67,46.8 U516.3
N18011662: length 11
  TOP w0.267: RN4.12 35.81,40.04 39.17,43.4 39.17,45.53 38.31,46.4 U516.2
N18011664: length 9.9
  TOP w0.267: U516.1 37.94,46 38.31,45.63 38.31,43.46 35.31,40.46 RN4.13
N18011666: length 5.5
  TOP w0.267: RN4.14 34.81,40.12 33.59,41.34 U516.126
N18011668: length 5.4
  TOP w0.267: RN4.15 34.31,39.99 33.19,41.1 U516.125
N18011670: length 5.4
  TOP w0.267: RN4.16 33.81,39.85 32.79,40.87 U516.124
N18041897: length 5.8
  TOP w0.508: C626.1 R586.1 30.41,27.35 R588.2 29.09,26.26 29.43,25.93 29.95,25.93 U512.5
N18041909: length 9.6
  TOP w0.508: C624.1 38.49,28.34 37.98,28.84 C626.2 R586.2
N28326141: length 4.5
  TOP w0.267: C681.2 R628.2 16.26,33.78 17.13,32.91 U517.5
N28326313: length 3.1
  TOP w0.267: R621.1 19.05,33.91 18.15,33.01 U517.3
N28326316: length 2.2
  TOP w0.267: R625.2 17.13,20.84 U517.32
N28326449: length 3.7
  TOP w0.267: R620.1 20.45,33.91 19.68,33.15 19.28,33.15 18.63,32.49 U517.2
N28326927: length 9.8
  TOP w0.267: v1(17.03,29.77) 17.03,28.69 17.69,28.03 18.67,28.03 19.13,27.57 U517.43
  BOTTOM w0.267: R618.1 19.94,31.88 17.84,29.77 v1(17.03,29.77)
N28326930: length 6.3
  TOP w0.267: v1(18.03,28.7) 18.85,28.7 19.49,28.05 U517.44
  BOTTOM w0.267: v1(18.03,28.7) 19.56,30.23 R615.1
N28358514: length 5
  TOP w0.267: U516.70 17.26,56.4 16.89,56.03 R39.2
N28456981: length 1.7
  TOP w0.267: C796.2 16.8,74.86 U518.6
N28456983:
  vias: v1(21.93,82.68) v1(23.2,82.68) v1(24.47,82.68) v1(25.74,82.68) v1(27.01,82.68) v1(28.28,82.68)
N28457010: length 17.3
  TOP w0.508: C799.1 v1(13,75.11) 13,70.7 14.48,69.23 14.48,66.65 15.11,66.02 18.8,66.02 19.48,66.7 C801.2
  BOTTOM w0.508: C799.1 v1(13,75.11)
  vias: v1(20.59,68.71) v1(20.59,67.44) v1(21.86,68.71) v1(21.86,67.44) v1(24.4,68.71) v1(25.67,68.71)
N28457030: length 5.4
  TOP w0.508: v1(12.19,76.79) C799.2 R634.1 16.81,76.79 U518.4
  BOTTOM w0.508: C799.2 v1(12.19,76.79)
N28459422: length 7.4
  TOP w0.267: U518.5 15.77,75.83 v1(15.16,75.22) ; R635.1 v1(13.22,78.5)
  BOTTOM w0.508: v1(15.16,75.22) 14.36,76.02 14.36,77.83 13.69,78.5 v1(13.22,78.5)
N270050601: length 1.5
  BOTTOM w0.267: R500.2 Q500.2

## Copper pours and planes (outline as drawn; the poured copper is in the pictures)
GND on TOP: 40.32,28.01 40.32,25.32 39.86,24.86 39.86,23.54 39.95,23.44 44.48,23.44 44.83,23.09 44.83,20.78 44.35,20.3 40.11,20.3 39.04,21.37 32.45,21.37 31.82,22 31.82,23.29 31.74,23.36 31.21,23.36 31.14,23.29 31.14,22.01 30.6,21.47 30.6,19.12 31.5,18.21 46.94,18.21 47.36,18.62 47.36,27.65 46.61,28.39 40.71,28.39
GND on TOP: 50.52,56.24 56.55,56.24 56.75,56.45 56.75,57.26 56.97,57.48 56.97,58.46 57.17,58.66 59.09,58.66 59.26,58.5 59.26,53.5 59.06,53.3 56.89,53.3 56.72,53.47 56.72,54.51 56.66,54.57 53.77,54.57 53.42,54.22 53.42,51.65 53.15,51.38 50.43,51.38 50.23,51.58 50.23,55.95
GND on TOP: 1.27,1.27 1.27,78.65 0.13,79.79 0.13,83.13 1.85,84.86 5.09,84.86 6.23,83.72 54.29,83.72 55.43,84.86 58.72,84.86 60.4,83.18 60.4,79.8 59.26,78.65 59.26,18.26 55.28,18.26 54.14,17.12 50.84,17.12 49.7,18.26 47.73,18.26 47.73,1.27 ; 16 cut-outs
GND on TOP: 18.92,75.23 20.57,75.23 20.73,75.07 20.73,71.31 20.46,71.04 18.73,71.04 18.36,70.68 18.36,66.8 18.05,66.48 15.84,66.48 15.55,66.77 15.55,71.9 16.07,72.43 18.58,72.43 18.82,72.67 18.82,75.13
GND on BOTTOM: 58.35,57.31 58.35,51.77 57.74,51.17 50.54,51.17 50.15,51.55 50.15,54.93 49.34,55.74 49.34,56.84 49.7,57.19 51.4,57.19 51.94,56.65 53.94,56.65 54.32,57.03 54.32,62.45 54.66,62.78 55.52,62.78 55.69,62.61 55.69,61.46 55.35,61.11 55.35,58.19 55.71,57.83 57.83,57.83
GND on BOTTOM: 59.19,44 59.19,48.64 59.01,48.81 56.55,48.81 56.29,48.55 56.29,43.92 56.42,43.79 58.98,43.79
GND on BOTTOM: 15.36,74.47 21.8,74.47 22.11,74.15 22.11,70.97 21.55,70.41 19.25,70.41 18.3,69.45 18.3,66.29 17.93,65.93 16.05,65.93 15.89,66.09 15.89,70.52 14.87,71.53 14.87,73.98
GND on BOTTOM: 16.12,41.16 18.21,41.16 18.47,41.41 18.47,43.74 18.21,44 16.12,44 15.87,43.74 15.87,41.41
GND on BOTTOM: 1.27,1.27 1.27,78.65 0.13,79.79 0.13,83.13 1.85,84.86 5.09,84.86 6.23,83.72 54.29,83.72 55.43,84.86 58.72,84.86 60.4,83.18 60.4,79.8 59.26,78.65 59.26,18.26 55.28,18.26 54.14,17.12 50.84,17.12 49.7,18.26 47.73,18.26 47.73,1.27 ; 2 cut-outs
GND on 02_GND1, 03_SIG1, 04_GND2, 06_PWR, 07_GND3: 1.27,1.27 1.27,78.65 0.13,79.79 0.13,83.13 1.85,84.86 5.09,84.86 6.23,83.72 54.29,83.72 55.43,84.86 58.72,84.86 60.4,83.18 60.4,79.8 59.26,78.65 59.26,18.26 55.28,18.26 54.14,17.12 50.84,17.12 49.7,18.26 47.73,18.26 47.73,1.27
GND on 05_SIG2: 1.27,1.27 1.27,78.65 0.13,79.79 0.13,83.13 1.85,84.86 5.09,84.86 6.23,83.72 54.29,83.72 55.43,84.86 58.72,84.86 60.4,83.18 60.4,79.8 59.26,78.65 59.26,18.26 55.28,18.26 54.14,17.12 50.84,17.12 49.7,18.26 47.73,18.26 47.73,1.27 ; 3 cut-outs
P5V on TOP: 12.79,17.19 10.87,17.19 10.61,16.94 10.61,14.68 10.87,14.42 12.79,14.42 12.98,14.62 12.98,17
P5V on TOP: 20.21,76.45 20.77,77.02 20.77,79.94 20.5,80.22 15.79,80.22 15.48,79.91 15.48,77.83 15.93,77.38 17.59,77.38 17.7,77.28 17.7,76.56 17.81,76.45
P5V on TOP: 49.71,74.57 52.43,74.57 52.69,74.83 52.69,81.73 52.25,82.17 50.26,82.17 49.45,81.36 49.45,74.83
P5V on TOP: 26.84,24.1 26.84,19.51 27.21,19.15 29.55,19.15 29.8,19.4 29.8,21.08 30.87,22.15 30.87,23.39 31.19,23.7 32.11,23.7 32.85,24.44 32.85,25.79 32.54,26.09 31.45,26.09 31.17,25.81 31.17,24.73 30.96,24.52 27.25,24.52
P5V on TOP: 49.36,57.18 52.4,57.18 52.69,57.48 52.69,59.35 51.67,60.37 49.35,60.37 49.11,60.13 49.11,57.44
P5V on BOTTOM: 15.42,76.1 21.72,76.1 21.97,76.35 21.97,80.1 21.72,80.35 15.42,80.35 15.16,80.1 15.16,76.35
P5V on BOTTOM: 27.42,21.04 29.62,21.04 29.87,21.3 29.87,24.51 29.62,24.76 27.42,24.76 27.17,24.51 27.17,21.3
P5V on BOTTOM: 52.69,60.74 52.62,60.81 51.69,60.81 51.26,60.38 49.32,60.38 49.05,60.1 49.05,57.66 49.21,57.49 52.39,57.49 52.69,57.79
P5V on BOTTOM: 50.84,74.32 52.73,74.32 52.99,74.58 52.99,82.19 52.73,82.45 50.51,82.45 50.27,82.2 50.27,74.89
P5V on BOTTOM: 10.66,14.7 13.06,14.7 13.31,14.96 13.31,16.94 13.06,17.2 10.66,17.2 10.4,16.94 10.4,14.96
P5V on 05_SIG2: 49.88,56.8 48.76,57.93 48.76,69.88 47.44,71.21 44.79,71.21 44.09,71.9 44.09,73.9 45.09,74.89 45.09,76.1 44.38,76.81 11.3,76.81 10.78,77.33 10.78,82.53 11.82,83.57 51.31,83.57 52.61,82.27 52.61,78.22 59.26,71.57 59.26,57.17 58.89,56.8
P5V on 06_PWR: 2.18,77.66 4.22,79.69 5.39,81.24 4.64,83.03 56.68,83.03 59.18,80.53 59.18,51.04 58.6,50.46 54.62,50.46 53.18,51.9 49.39,51.9 48.86,52.43 48.86,60.49 52.48,64.11 52.48,67.79 49.06,71.22 45.03,71.22 42.44,73.81 13.02,73.81 8.38,69.17 8.38,59.69 6.1,57.4 6.1,50.8 9.91,46.99 9.91,31.93 11.06,30.77 26.58,30.77 31.82,25.54 31.82,16.73 29.48,14.39 4.99,14.39 2.18,17.2 ; 3 cut-outs
P5V_HDMI0 on TOP: 48.4,47.54 50.15,47.54 50.4,47.79 50.4,48.91 50.15,49.16 48.4,49.16 48.15,48.91 48.15,47.79
P5V_HDMI0 on BOTTOM: 53.17,47.5 53.47,47.8 53.47,49.16 53.31,49.33 48.33,49.33 48.15,49.15 48.15,47.76 48.41,47.5
P5V_LAB on TOP: 53.18,77.4 53.18,73.9 53.43,73.65 55.57,73.65 56.02,73.2 56.02,70.78 56.44,70.36 59.01,70.36 59.22,70.58 59.22,77.3 58.9,77.62 53.41,77.62
P5V_LAB on BOTTOM: 54.52,73.57 55.57,73.57 55.97,73.17 55.97,70.68 56.57,70.08 58.63,70.08 59.24,70.68 59.24,77.54 58.98,77.79 54.52,77.79 54.27,77.54 54.27,73.83
P5V_MAIN on TOP: 8.89,13.17 9.53,13.17 9.65,13.29 9.65,14.34 10.08,14.77 10.08,16.24 9.8,16.52 8.21,16.52 8.03,16.34 8.03,14.77 8.75,14.05 8.75,13.3
P5V_MAIN on BOTTOM: 7.97,16.62 9.42,16.62 9.64,16.4 9.64,13.25 9.53,13.14 8.82,13.14 8.65,13.32 8.65,14 7.81,14.83 7.81,16.46
P5V_MAIN on 03_SIG1: 7.86,11.5 9.67,11.5 10.23,12.06 10.23,16.52 9.62,17.13 7.86,17.13 7.61,16.88 7.61,11.75
P3P3V_AFE on TOP: 48.53,60.61 51.52,60.61 51.78,60.86 51.78,62.45 51.52,62.7 48.53,62.7 48.28,62.45 48.28,60.86
P3P3V_AFE on TOP: 49.18,36.78 51.06,36.78 51.17,36.68 51.17,35.06 51.36,34.87 52.11,34.87 52.27,35.03 52.27,37.16 51.97,37.46 49.18,37.46 49.07,37.35 49.07,36.89
P3P3V_AFE on BOTTOM: 50.3,62.91 50.04,63.16 48.11,63.16 47.86,62.91 47.86,61 48.18,60.68 50.03,60.68 50.3,60.94
P3P3V_AFE on BOTTOM: 50.1,34.97 51.98,34.97 52.23,35.23 52.23,36.6 51.98,36.85 50.1,36.85 49.84,36.6 49.84,35.23
P3P3V_AFE on 03_SIG1: 47.29,64.07 47.29,57.95 50.08,55.16 50.08,45.79 48.83,44.53 48.83,37.62 50.84,35.61 50.84,31.36 51.61,30.59 57.09,30.59 57.84,31.34 57.84,35.2 57.19,35.85 55.39,35.85 54.64,35.1 54.64,33.96 54.22,33.55 53.31,33.55 52.78,34.07 52.78,38.51 53.26,38.98 53.26,44.6 57.67,49.01 57.67,63.95 56.37,65.25 48.47,65.25
P3P3V_AFE on 06_PWR: 50.53,32.06 49.12,33.46 49.12,50.9 49.41,51.19 52.92,51.19 54.29,49.82 58.29,49.82 59.26,48.86 59.26,33.8 57.52,32.06
P3P3V_ITE on TOP: 44.93,56.53 48.37,56.53 48.48,56.63 48.48,58.99 48.37,59.09 44.93,59.09 44.68,58.83 44.68,56.78
P3P3V_ITE on TOP: 49.57,63.34 51.58,63.34 51.7,63.45 51.7,67.92 51.41,68.2 49.7,68.2 49.37,67.88 49.37,63.53
P3P3V_ITE on BOTTOM: 49.52,64.6 51.41,64.6 51.67,64.85 51.67,68.07 51.41,68.32 49.52,68.32 49.26,68.07 49.26,64.85
P3P3V_ITE on BOTTOM: 9.15,33.19 12.14,33.19 12.45,33.5 12.45,36.41 12.29,36.57 9.11,36.57 8.85,36.32 8.85,33.49
P3P3V_ITE on BOTTOM: 46.21,56.44 48.3,56.44 48.55,56.7 48.55,58.65 48.3,58.9 46.21,58.9 45.95,58.65 45.95,56.7
P3P3V_ITE on 03_SIG1: 14.37,38.33 17.24,38.33 17.54,38.03 17.54,33.92 17.23,33.61 13.33,33.61 13.19,33.46 13.19,31.66 13.47,31.38 21.98,31.38 23.09,30.27 23.09,17.48 21.46,15.85 14.04,15.85 12.33,17.56 7.54,17.56 7.05,17.07 7.05,14.93 6.76,14.63 2.61,14.63 2.12,15.13 2.12,35.66 3.47,37.02 13.78,37.02 14.18,37.42 14.18,38.14
P3P3V_ITE on 06_PWR: 6.6,50.8 6.6,57.15 8.94,59.48 8.94,68.53 13.83,73.43 42.19,73.43 45.06,70.56 49.29,70.56 51.55,68.3 51.55,63.97 48.34,60.77 48.34,55.89 47.92,55.47 36.5,55.47 34.4,57.57 34.4,66.26 33.44,67.22 24.52,67.22 23.99,66.68 23.99,52.55 27.43,49.11 27.43,32.1 26.75,31.42 11.76,31.42 10.41,32.77 10.41,46.99
P3P3V_LAB on TOP: 49.62,72.85 54.93,72.85 55.37,72.42 55.37,70.59 55.17,70.38 52.14,70.38 51.62,70.91 49.73,70.91 49.44,71.19 49.44,72.67
P3P3V_LAB_RES on TOP: 52.09,60.45 53.03,59.52 53.03,57.49 53.27,57.24 54.15,57.24 54.3,57.39 54.3,64.65 55.76,66.11 55.76,69.6 55.41,69.95 51.95,69.95 51.43,70.47 49.55,70.47 49.43,70.36 49.43,68.71 49.56,68.59 51.59,68.59 52.09,68.08
P3P3V_LAB_RES on BOTTOM: 54.88,63.47 54.06,62.65 54.06,57.56 53.9,57.39 53.28,57.39 53.07,57.61 53.07,60.97 52.81,61.23 52.61,61.23 52.09,61.75 52.09,68.55 51.8,68.84 50.71,68.84 50.43,69.12 50.43,70.86 50.68,71.1 54.17,71.1 55.62,69.66 55.62,66.45 54.88,65.72
RX_1V2 on TOP: 39.89,22.91 39.89,21.09 40.19,20.78 44.34,20.78 44.57,21.02 44.57,22.92 44.36,23.13 40.11,23.13
RX_1V2 on TOP: 27.86,66.58 27.86,64.81 27.55,64.51 24.86,64.51 24.44,64.93 24.44,66.65 24.67,66.88 27.55,66.88
RX_1V2 on BOTTOM: 40.76,20.74 44.31,20.74 44.57,21 44.57,22.84 44.31,23.1 40.76,23.1 40.51,22.84 40.51,21
RX_1V2 on BOTTOM: 25.28,67.88 27.56,67.88 27.91,67.53 27.91,64.82 27.71,64.63 24.8,64.63 24.55,64.88 24.55,67.14
RX_1V2 on BOTTOM: 16.93,38.05 18.95,38.05 19.21,38.31 19.21,40.58 18.95,40.84 16.93,40.84 16.68,40.58 16.68,38.31
RX_1V2 on BOTTOM: 18.82,58.03 19.07,58.29 19.07,60.46 18.71,60.83 10.03,60.83 9.4,60.2 9.4,58.42 9.78,58.03
RX_1V2 on 03_SIG1: 21.85,67.4 27.66,67.4 28.88,66.18 28.88,62.18 26.69,60 22.82,60 21.79,58.97 17.27,58.97 14.96,56.65 14.96,45.91 17.93,42.93 17.93,39.34 17.48,38.88 12.35,38.88 11.87,38.41 10.16,38.41 8.53,40.04 8.53,61.9 9.35,62.72 17.18,62.72
RX_1V2 on 06_PWR: 24.64,66.57 33.06,66.57 33.48,66.15 33.48,57.5 36.33,54.64 47.5,54.64 48.11,54.04 48.11,23.02 45.46,20.38 32.86,20.38 32.45,20.79 32.45,25.49 27.84,30.1 27.84,49.42 24.44,52.82 24.44,66.37
RX_AVCC12 on TOP: 10.04,64.99 10.42,64.99 10.67,65.24 12.44,65.24 12.58,65.1 12.58,62.97 12.36,62.76 10.01,62.76 9.8,62.97 9.8,64.75
RX_AVCC33 on TOP: 41.86,56.65 43.92,56.65 44.17,56.9 44.17,61.24 43.92,61.49 41.86,61.49 41.61,61.24 41.61,56.9
RX_AVCC33 on 03_SIG1: 28.54,55.75 28.53,55.79 28.16,56.16 27.65,56.04 27.58,56.02 27.52,56.04 27.01,56.16 26.64,55.79 26.63,55.75 25.46,55.75 22.81,58.4 22.81,59.18 22.94,59.31 27.22,59.31 27.56,58.97 27.56,58.58 27.56,58.58 28.07,57.89 28.58,58.58 28.58,58.58 28.58,58.97 31.33,61.72 33.99,61.72 34.12,61.85 34.48,61.85 34.56,61.81 34.57,61.71 35.08,61.01 35.58,61.71 35.6,61.81 35.68,61.85 42.64,61.85 43.33,61.16 43.33,57.24 42.63,56.54 41.66,56.54 41.17,57.03 37.55,57.03 36.27,55.75
RX_IVDD12 on BOTTOM: 31.51,40.68 31.51,40.93 31.59,41.6 31.01,41.96 30.94,41.99 30.91,42.06 30.91,43.18 29.34,43.18 29.34,41.66 29.49,41.66 29.49,40.28 29.55,40.22 29.55,38.61 29.24,38.31 20.04,38.31 19.63,38.71 19.63,40.94 19.47,41.11 19.47,44.35 20,44.88 24.36,44.88 24.36,44.09 24.79,43.65 24.79,43.31 23.19,43.31 23.19,41.78 26.21,41.78 26.21,43.31 26.06,43.31 26.06,44.18 25.63,44.61 25.63,44.88 33.27,44.88 33.86,45.47 36.23,45.47 36.9,46.14 36.9,48.22 36.58,48.54 35.54,48.54 34.96,49.12 34.28,49.12 34.19,49.14 34.11,49.15 34.04,49.18 34.01,49.25 34.01,50.14 34.24,50.36 34.65,50.27 35,50.52 39.04,50.52 39.83,49.73 39.83,42.62 38.82,41.61 33.87,41.61 32.75,40.49 31.7,40.49
RX_IVDD12 on 03_SIG1: 21.92,40.4 16.27,46.06 16.27,50.33 16.26,50.35 16.26,51.64 16.76,52.15 18.77,52.15 20.17,50.75 20.17,47.84 23.54,44.47 32.5,44.47 33.03,43.93 33.03,41.07 32.37,40.4
RX_IVDD12 on 05_SIG2: 33.79,55.45 35.5,55.45 36.07,56.01 39.06,56.01 39.64,55.43 39.64,46.6 37.88,44.85 37.88,42.44 35.47,40.02 21.92,40.02 15.03,46.91 15.03,55.14 15.45,55.57 18.4,55.57 19.53,54.43 19.53,53.38 21.3,51.61 21.3,49.93 25.03,46.2 31.01,46.2 32.79,47.99 32.79,54.45
RX_OVDD on BOTTOM: 7.01,54.79 16.41,54.79 17.33,53.87 17.33,53.67 16.18,52.51 16.18,51.63 16.11,51.56 15.03,51.56 14.12,52.47 7.58,52.47 6.8,53.25 6.8,54.58
RX_OVDD on 03_SIG1: 24.16,45.01 20.73,48.44 20.73,50.95 18.78,52.9 16.52,52.9 15.88,53.54 15.88,56.77 17.45,58.34 22.07,58.34 23.58,56.83 23.58,55.64 24.31,54.91 33.58,54.91 35.61,52.88 35.61,47.78 32.84,45.01
N18041909 on TOP: 33.54,27.83 33.54,25.92 33.72,25.74 37.17,25.74 37.7,25.2 37.7,21.78 37.89,21.58 39.19,21.58 39.43,21.82 39.43,27.64 39.04,28.02 33.72,28.02
N28289603 on TOP: 32.19,23.32 32.19,22.18 32.75,21.62 36.91,21.62 37.22,21.93 37.22,24.7 37.07,24.85 33.71,24.85
N28456983 on TOP: 17.61,72.71 17.49,72.83 17.49,73.8 17.65,73.96 17.65,75.77 18.09,76.2 20.34,76.2 21.49,77.35 21.49,83 21.8,83.31 28.4,83.31 28.81,82.91 28.81,76.49 27.82,75.51 18.79,75.51 18.7,75.43 18.7,72.83 18.58,72.71
N28456983 on BOTTOM: 21.1,80.81 30.4,80.81 30.65,81.06 30.65,83.19 30.4,83.44 21.1,83.44 20.85,83.19 20.85,81.06
N28457010 on TOP: 23.53,72.28 27.81,72.28 28.2,71.89 28.2,68.92 27.61,68.33 24.78,68.33 23.46,67 19.08,67 18.88,67.21 18.88,70.66 19,70.78 22.03,70.78
N28457010 on BOTTOM: 19.98,66.78 23.18,66.78 24.65,68.24 27.85,68.24 28.14,68.52 28.14,70.64 27.68,71.09 22.78,71.09 21.16,69.47 20.04,69.47 19.61,69.05 19.61,67.14

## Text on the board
BOTTOM: 08_BOTTOM
Board Geometry/Soldermask Bottom: SOLDERMASK_BOTTOM
Ref Des/Silkscreen Bottom: 1 | SIP_VDD | 305-PD-23-0762 | AUG-2023 | SILKSCREEN_BOTTOM | SILKSCREEN - SECONDARY SIDE | 10
TOP: 01_TOP
Board Geometry/Soldermask Top: SOLDERMASK_TOP
Ref Des/Silkscreen Top: 1 | 2 | R | TM | 14 | 13 | 50 | 26 | 51 | 25 | 75 | 76 | 100 | 11 | 12 | 4 | GND | SCDT | 3 | 7 | TEXAS INSTRUMENTS | TEXAS INSTRUMENTS-DLP   PRODUCTS | ASSY 2509764 REV[  ] | PWB  2509763 REV[  ] | MSN[     ] | DLP  PRODUCTS | DLPC4430EVM | FRONT END BOARD | DLP110A | SCH  2509762 | AFE1000 REFERENCE DESIGN | MADE IN U.S.A. | FOR EVALUATION ONLY, | NOT FCC APPROVED | FOR RESALE. | SILKSCREEN_TOP | SILKSCREEN - PRIMARY SIDE | 9
02_GND1: 02-GND1
03_SIG1: 03_SIG1
04_GND2: 04_GND2
05_SIG2: 05_SIG2
06_PWR: 06_PWR
07_GND3: 07_GND3
DIMENSION: 02_GND1 | 03_SIG1 | 04_GND2 | 05_SIG2 | 07_GND3 | 06_PWR | BOTTOM | TOP | (OZ) | PASTEMASK_TOP | REFER NOTE: 9 | 1. PLATE ALL EXPOSED AREAS WITH ELECTROLESS | IMMERSION GOLD, NICKEL 150 MICROINCHES THK MIN | GOLD 5-15 MICROINCHES THK MIN. | 10. MARKED REGION DRILLS NEED TO BE SOLDERMASK PLUGGING ON BOTTOM SIDE | 11. CLIP SILKSCREEN ON NO MASK AREA | 12. NO VENDOR LOGO, ART WORKS SHOULD NOT BE | 14. PLATED THROUGH SLOT INDICATED WITH MULTIPLE DRILL HITS SHOULD BE | 13. REMOVE UNUSED PADS IN ALL INNER LAYERS | 6. ALL HOLES IN DRILL CHART ARE FINISHED HOLE SIZES (FHS)." | CHANGED WITHOUT PRIOR APPROVAL FROM PACTRON | FINISHED AS SMOOTH WALL BY VEDOR. | LAYER# | COPPER WEIGHT | HALF+PLATING | 2 | 1 | IMPEDANCE CONTROL | +/- 10% | 50ohm SINGLE ENDED | TRACE WIDTH | 10.5 | 5.8 | 4 | FAB | TRACE WIDTH / SPACE | 100ohm DIFFERENTIAL | 4.5/4.5 | LAYER STACK-UP - ALL DIMENSIONS IN MILS
BODY_CENTER: PASTEMASK_BOTTOM
User.11: 19 | TOP SIDE VIA PLUG
User.21: 13 | REFERENCE DESIGN | AFE1000/IT6535 | 2511801 | A | 29-4-2013 | TEXAS INSTRUMENTS
